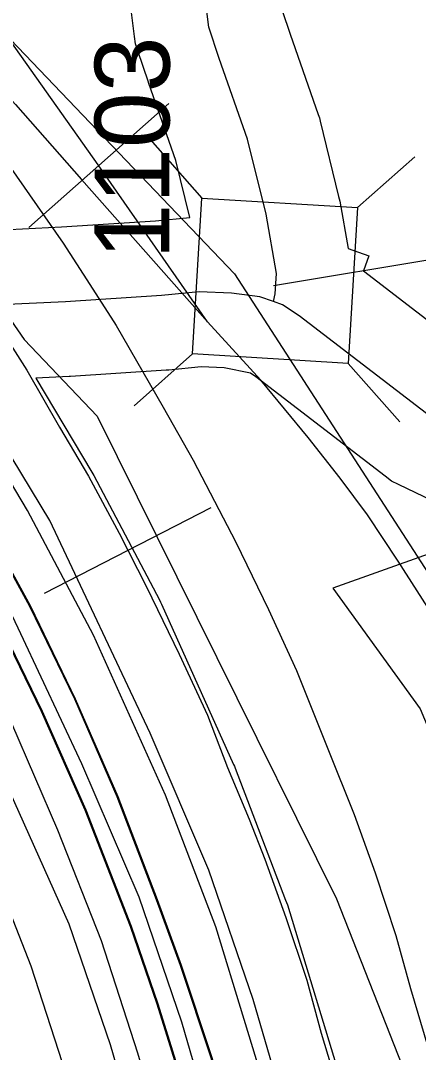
# Model space of a CAD drawing. Extents: x -132.8 to -73.3, y -60 to -26.
# Drawn here: x -123.3422 to -123.1827, y -46.015 to -45.6018 of the extents above; entities that cross this region are included whole.
import ezdxf

# ---------------------------------------------------------------- set-up
doc = ezdxf.new("R2010")
doc.units = 0
for name, color, linetype in [('tdCoDivCarto', 7, 'Continuous'), ('tdCoHydroRiver', 7, 'Continuous'), ('tdCoInt', 7, 'Continuous'), ('tdCoIntCL', 7, 'Continuous'), ('tdCoIntRte', 7, 'Continuous'), ('tdCoPrimary', 7, 'Continuous'), ('tdCoRRCL', 7, 'Continuous'), ('tdCoSecRdNmbr', 7, 'Continuous'), ('tdCoSecRteBand', 7, 'Continuous'), ('tdCoSecRteCL', 7, 'Continuous'), ('tdCoStrucSec', 7, 'Continuous'), ('tdCoStrucSecFHWANum', 7, 'Continuous'), ('tdCoSurfBitum', 7, 'Continuous'), ('tdCoSurfGravel', 7, 'Continuous')]:
    doc.layers.add(name, color=color, linetype=linetype)

msp = doc.modelspace()

# ---------------------------------------------------------------- linework, layer by layer
at = {"layer": 'tdCoDivCarto'}
for p, q in [((-123.33816, -45.83648), (-123.36405, -45.78914)), ((-123.35754, -45.82933), (-123.33362, -45.87841)), ((-123.32016, -45.87348), (-123.33816, -45.83648)), ((-123.30314, -45.91269), (-123.32016, -45.87348)), ((-123.33362, -45.87841), (-123.31611, -45.91786)), ((-123.28736, -45.95387), (-123.30314, -45.91269)), ((-123.31611, -45.91786), (-123.29786, -45.96447)), ((-123.27774, -45.98026), (-123.28736, -45.95387)), ((-123.29786, -45.96447), (-123.28725, -45.99555)), ((-123.26541, -46.01725), (-123.27774, -45.98026)), ((-123.28725, -45.99555), (-123.27542, -46.03328))]:
    msp.add_line(p, q, dxfattribs=at)
for points in [[(-123.68659, -45.35046), (-123.65626, -45.39214), (-123.63078, -45.42835), (-123.578, -45.5011), (-123.49194, -45.6244), (-123.43842, -45.69986), (-123.4113, -45.73883), (-123.38516, -45.78001), (-123.35754, -45.82933), (-123.33362, -45.87841), (-123.31611, -45.91786), (-123.29786, -45.96447), (-123.28725, -45.99555), (-123.27542, -46.03328), (-123.26259, -46.08161), (-123.25544, -46.11416), (-123.24829, -46.15239), (-123.24459, -46.17754), (-123.23152, -46.27051), (-123.22903, -46.28875)], [(-123.68659, -45.35046), (-123.65626, -45.39214), (-123.63078, -45.42835), (-123.578, -45.5011), (-123.49194, -45.6244), (-123.43842, -45.69986), (-123.4113, -45.73883), (-123.38516, -45.78001), (-123.35754, -45.82933), (-123.33362, -45.87841), (-123.31611, -45.91786), (-123.29786, -45.96447), (-123.28725, -45.99555), (-123.27542, -46.03328), (-123.26259, -46.08161), (-123.25544, -46.11416), (-123.24829, -46.15239), (-123.24459, -46.17754), (-123.23152, -46.27051), (-123.22903, -46.28875)], [(-123.68659, -45.35046), (-123.65626, -45.39214), (-123.63078, -45.42835), (-123.578, -45.5011), (-123.49194, -45.6244), (-123.43842, -45.69986), (-123.4113, -45.73883), (-123.38516, -45.78001), (-123.35754, -45.82933), (-123.33362, -45.87841), (-123.31611, -45.91786), (-123.29786, -45.96447), (-123.28725, -45.99555), (-123.27542, -46.03328), (-123.26259, -46.08161), (-123.25544, -46.11416), (-123.24829, -46.15239), (-123.24459, -46.17754), (-123.23152, -46.27051), (-123.22903, -46.28875)], [(-123.21499, -46.28682), (-123.22645, -46.20393), (-123.23187, -46.16694), (-123.2373, -46.13315), (-123.24593, -46.09172), (-123.25752, -46.04363), (-123.26541, -46.01725), (-123.27774, -45.98026), (-123.28736, -45.95387), (-123.30314, -45.91269), (-123.32016, -45.87348), (-123.33816, -45.83648), (-123.36405, -45.78914), (-123.39463, -45.73957), (-123.4299, -45.68803), (-123.47552, -45.62366), (-123.5172, -45.56448), (-123.59438, -45.45794), (-123.61855, -45.42416), (-123.66037, -45.36362)], [(-123.21499, -46.28682), (-123.22645, -46.20393), (-123.23187, -46.16694), (-123.2373, -46.13315), (-123.24593, -46.09172), (-123.25752, -46.04363), (-123.26541, -46.01725), (-123.27774, -45.98026), (-123.28736, -45.95387), (-123.30314, -45.91269), (-123.32016, -45.87348), (-123.33816, -45.83648), (-123.36405, -45.78914), (-123.39463, -45.73957), (-123.4299, -45.68803), (-123.47552, -45.62366), (-123.5172, -45.56448), (-123.59438, -45.45794), (-123.61855, -45.42416), (-123.66037, -45.36362)], [(-123.21499, -46.28682), (-123.22645, -46.20393), (-123.23187, -46.16694), (-123.2373, -46.13315), (-123.24593, -46.09172), (-123.25752, -46.04363), (-123.26541, -46.01725), (-123.27774, -45.98026), (-123.28736, -45.95387), (-123.30314, -45.91269), (-123.32016, -45.87348), (-123.33816, -45.83648), (-123.36405, -45.78914), (-123.39463, -45.73957), (-123.4299, -45.68803), (-123.47552, -45.62366), (-123.5172, -45.56448), (-123.59438, -45.45794), (-123.61855, -45.42416), (-123.66037, -45.36362)]]:
    msp.add_lwpolyline(points, dxfattribs=at)
at = {"layer": 'tdCoHydroRiver'}
msp.add_lwpolyline([(-122.72845, -45.73825), (-122.82597, -45.78451), (-122.87849, -45.80044), (-123.04289, -45.81019), (-123.11745, -45.82394), (-123.12674, -45.81738), (-123.15965, -45.8086), (-123.21702, -45.82913), (-123.18202, -45.87741), (-123.1746, -45.89497), (-123.15487, -45.9239), (-123.1249, -45.98308), (-123.11897, -45.99744), (-123.10673, -46.01197), (-123.07532, -46.07593), (-123.05246, -46.1649), (-123.0467, -46.18556), (-123.0436, -46.18722), (-123.02978, -46.26017), (-123.01499, -46.29686)], dxfattribs=at)
at = {"layer": 'tdCoInt'}
for points in [[(-123.19689, -47.64969), (-123.15587, -47.57914), (-123.13025, -47.51594), (-123.10652, -47.38398), (-123.1111, -47.00162), (-123.11448, -46.89262), (-123.12468, -46.76865), (-123.21401, -46.12989), (-123.22788, -46.06626), (-123.24899, -45.99383), (-123.26669, -45.94208), (-123.2903, -45.88715), (-123.33052, -45.80193), (-123.37601, -45.72709), (-123.50419, -45.54213), (-123.69017, -45.28281)], [(-123.29698, -47.69009), (-123.24768, -47.61769), (-123.20987, -47.55265), (-123.1882, -47.49918), (-123.16657, -47.37891), (-123.17109, -47.00292), (-123.17443, -46.89512), (-123.1843, -46.77553), (-123.27313, -46.14041), (-123.28606, -46.08107), (-123.30621, -46.01194), (-123.32272, -45.96367), (-123.36923, -45.86024), (-123.38334, -45.83056), (-123.42644, -45.75965), (-123.55308, -45.57692), (-123.74046, -45.31564)]]:
    msp.add_lwpolyline(points, dxfattribs=at)
at = {"layer": 'tdCoIntCL'}
msp.add_lwpolyline([(-123.17972, -46.59078), (-123.22232, -46.28778), (-123.22859, -46.24315), (-123.24357, -46.13515), (-123.25697, -46.07366), (-123.2776, -46.00289), (-123.29471, -45.95288), (-123.31767, -45.89945), (-123.3421, -45.84743), (-123.35693, -45.81624), (-123.36969, -45.7954), (-123.40123, -45.74337), (-123.47655, -45.63373), (-123.52863, -45.55953), (-123.52868, -45.55946), (-123.63292, -45.41411), (-123.64916, -45.39147), (-123.68187, -45.34586)], dxfattribs=at)
at = {"layer": 'tdCoIntRte'}
for points in [[(-123.68697, -45.35046), (-123.65664, -45.39214), (-123.63116, -45.42835), (-123.57838, -45.5011), (-123.49232, -45.6244), (-123.4388, -45.69986), (-123.41168, -45.73883), (-123.38554, -45.78001), (-123.35792, -45.82933), (-123.334, -45.87841), (-123.31649, -45.91786), (-123.29824, -45.96447), (-123.28763, -45.99555), (-123.2758, -46.03328), (-123.26297, -46.08161), (-123.25582, -46.11416), (-123.24867, -46.15239), (-123.24497, -46.17754), (-123.2319, -46.27051), (-123.22941, -46.28875), (-123.21858, -46.36792), (-123.21513, -46.39283), (-123.20083, -46.49764)], [(-123.68697, -45.35046), (-123.65664, -45.39214), (-123.63116, -45.42835), (-123.57838, -45.5011), (-123.49232, -45.6244), (-123.4388, -45.69986), (-123.41168, -45.73883), (-123.38554, -45.78001), (-123.35792, -45.82933), (-123.334, -45.87841), (-123.31649, -45.91786), (-123.29824, -45.96447), (-123.28763, -45.99555), (-123.2758, -46.03328), (-123.26297, -46.08161), (-123.25582, -46.11416), (-123.24867, -46.15239), (-123.24497, -46.17754), (-123.2319, -46.27051), (-123.22941, -46.28875), (-123.21858, -46.36792), (-123.21513, -46.39283), (-123.20083, -46.49764)], [(-123.18638, -46.49542), (-123.19699, -46.42144), (-123.21104, -46.31811), (-123.21537, -46.28682), (-123.22683, -46.20393), (-123.23225, -46.16694), (-123.23768, -46.13315), (-123.24631, -46.09172), (-123.2579, -46.04363), (-123.26579, -46.01725), (-123.27812, -45.98026), (-123.28774, -45.95387), (-123.30352, -45.91269), (-123.32054, -45.87348), (-123.33854, -45.83648), (-123.36443, -45.78914), (-123.39501, -45.73957), (-123.43028, -45.68803), (-123.4759, -45.62366), (-123.51757, -45.56448), (-123.59476, -45.45794), (-123.61893, -45.42416), (-123.66075, -45.36362)], [(-123.18638, -46.49542), (-123.19699, -46.42144), (-123.21104, -46.31811), (-123.21537, -46.28682), (-123.22683, -46.20393), (-123.23225, -46.16694), (-123.23768, -46.13315), (-123.24631, -46.09172), (-123.2579, -46.04363), (-123.26579, -46.01725), (-123.27812, -45.98026), (-123.28774, -45.95387), (-123.30352, -45.91269), (-123.32054, -45.87348), (-123.33854, -45.83648), (-123.36443, -45.78914), (-123.39501, -45.73957), (-123.43028, -45.68803), (-123.4759, -45.62366), (-123.51757, -45.56448), (-123.59476, -45.45794), (-123.61893, -45.42416), (-123.66075, -45.36362)]]:
    msp.add_lwpolyline(points, dxfattribs=at)
at = {"layer": 'tdCoPrimary'}
for points in [[(-123.68659, -45.35046), (-123.65626, -45.39214), (-123.63078, -45.42835), (-123.578, -45.5011), (-123.49194, -45.6244), (-123.43842, -45.69986), (-123.4113, -45.73883), (-123.38516, -45.78001), (-123.35754, -45.82933), (-123.33362, -45.87841), (-123.31611, -45.91786), (-123.29786, -45.96447), (-123.28725, -45.99555), (-123.27542, -46.03328), (-123.26259, -46.08161), (-123.25544, -46.11416), (-123.24829, -46.15239), (-123.24459, -46.17754), (-123.23152, -46.27051), (-123.22903, -46.28875)], [(-123.68659, -45.35046), (-123.65626, -45.39214), (-123.63078, -45.42835), (-123.578, -45.5011), (-123.49194, -45.6244), (-123.43842, -45.69986), (-123.4113, -45.73883), (-123.38516, -45.78001), (-123.35754, -45.82933), (-123.33362, -45.87841), (-123.31611, -45.91786), (-123.29786, -45.96447), (-123.28725, -45.99555), (-123.27542, -46.03328), (-123.26259, -46.08161), (-123.25544, -46.11416), (-123.24829, -46.15239), (-123.24459, -46.17754), (-123.23152, -46.27051), (-123.22903, -46.28875)], [(-123.68659, -45.35046), (-123.65626, -45.39214), (-123.63078, -45.42835), (-123.578, -45.5011), (-123.49194, -45.6244), (-123.43842, -45.69986), (-123.4113, -45.73883), (-123.38516, -45.78001), (-123.35754, -45.82933), (-123.33362, -45.87841), (-123.31611, -45.91786), (-123.29786, -45.96447), (-123.28725, -45.99555), (-123.27542, -46.03328), (-123.26259, -46.08161), (-123.25544, -46.11416), (-123.24829, -46.15239), (-123.24459, -46.17754), (-123.23152, -46.27051), (-123.22903, -46.28875), (-123.21821, -46.36792), (-123.21475, -46.39283), (-123.20045, -46.49764)], [(-123.21499, -46.28682), (-123.22645, -46.20393), (-123.23187, -46.16694), (-123.2373, -46.13315), (-123.24593, -46.09172), (-123.25752, -46.04363), (-123.26541, -46.01725), (-123.27774, -45.98026), (-123.28736, -45.95387), (-123.30314, -45.91269), (-123.32016, -45.87348), (-123.33816, -45.83648), (-123.36405, -45.78914), (-123.39463, -45.73957), (-123.4299, -45.68803), (-123.47552, -45.62366), (-123.5172, -45.56448), (-123.59438, -45.45794), (-123.61855, -45.42416), (-123.66037, -45.36362)], [(-123.21499, -46.28682), (-123.22645, -46.20393), (-123.23187, -46.16694), (-123.2373, -46.13315), (-123.24593, -46.09172), (-123.25752, -46.04363), (-123.26541, -46.01725), (-123.27774, -45.98026), (-123.28736, -45.95387), (-123.30314, -45.91269), (-123.32016, -45.87348), (-123.33816, -45.83648), (-123.36405, -45.78914), (-123.39463, -45.73957), (-123.4299, -45.68803), (-123.47552, -45.62366), (-123.5172, -45.56448), (-123.59438, -45.45794), (-123.61855, -45.42416), (-123.66037, -45.36362)], [(-123.186, -46.49542), (-123.19661, -46.42144), (-123.21066, -46.31811), (-123.2127, -46.3034), (-123.21499, -46.28682), (-123.22645, -46.20393), (-123.23187, -46.16694), (-123.2373, -46.13315), (-123.24593, -46.09172), (-123.25752, -46.04363), (-123.26541, -46.01725), (-123.27774, -45.98026), (-123.28736, -45.95387), (-123.30314, -45.91269), (-123.32016, -45.87348), (-123.33816, -45.83648), (-123.36405, -45.78914), (-123.39463, -45.73957), (-123.4299, -45.68803), (-123.47552, -45.62366), (-123.5172, -45.56448), (-123.59438, -45.45794), (-123.61855, -45.42416), (-123.66037, -45.36362)]]:
    msp.add_lwpolyline(points, dxfattribs=at)
at = {"layer": 'tdCoRRCL'}
for p, q in [((-123.28278, -45.63489), (-123.33893, -45.68461)), ((-123.33258, -45.83102), (-123.26583, -45.79683))]:
    msp.add_line(p, q, dxfattribs=at)
for points in [[(-124.56441, -39.58277), (-124.59502, -40.99697), (-124.62126, -41.69986), (-124.64443, -42.5874), (-124.61743, -42.70169), (-124.59894, -42.77948), (-124.57448, -42.87004), (-124.36447, -43.41034), (-124.28789, -43.62059), (-124.20724, -43.85618), (-124.00071, -44.40901), (-123.83109, -44.9246), (-123.75422, -45.12382), (-123.67243, -45.25532), (-123.34073, -45.72941), (-123.31155, -45.76015), (-123.21558, -45.95355), (-123.18597, -46.02848), (-123.11918, -46.43252), (-123.02482, -47.17174), (-122.96612, -47.70495)], [(-123.31114, -45.65953), (-123.45627, -45.45467), (-123.61223, -45.2604)], [(-123.59516, -45.34231), (-123.56501, -45.38032), (-123.5346, -45.41859), (-123.50026, -45.46028), (-123.44574, -45.52371), (-123.39593, -45.57903), (-123.34429, -45.63539), (-123.31777, -45.66533)], [(-123.57309, -45.34093), (-123.54714, -45.37632), (-123.51765, -45.41905), (-123.48815, -45.46178), (-123.45801, -45.50411), (-123.42786, -45.54645), (-123.40584, -45.57686), (-123.38382, -45.60726), (-123.35446, -45.64908), (-123.3251, -45.69089), (-123.31449, -45.7074), (-123.30387, -45.72392), (-123.285, -45.75655), (-123.27307, -45.77779), (-123.2559, -45.81068), (-123.24279, -45.83769), (-123.23152, -45.86206), (-123.21907, -45.89339), (-123.20845, -45.91974), (-123.20006, -45.94307), (-123.19167, -45.96823), (-123.18591, -45.98947), (-123.17883, -46.0128)], [(-123.60889, -45.35881), (-123.58294, -45.3942), (-123.52396, -45.47966), (-123.46367, -45.56433), (-123.41963, -45.62515), (-123.36091, -45.70877), (-123.33967, -45.7418), (-123.32657, -45.76461), (-123.31503, -45.78427), (-123.30271, -45.80707), (-123.2917, -45.82857), (-123.27859, -45.85557), (-123.26732, -45.87995), (-123.2592, -45.90092), (-123.25055, -45.92163), (-123.24425, -45.93762), (-123.23587, -45.96095), (-123.22748, -45.98612), (-123.22171, -46.00735), (-123.21463, -46.03068)], [(-123.56021, -45.37027), (-123.43616, -45.51551), (-123.2564, -45.70322), (-123.09102, -45.9584), (-122.94435, -46.26514), (-122.79504, -46.53094), (-122.75778, -46.61553), (-122.7491, -46.64573), (-122.73718, -46.67287), (-122.72843, -46.82139), (-122.77817, -47.57893), (-122.78529, -47.67024)], [(-122.83836, -46.4665), (-122.87322, -46.40896), (-122.9149, -46.33819), (-122.92211, -46.32639), (-122.94085, -46.29388), (-122.9651, -46.24866), (-122.98634, -46.20777), (-123.01216, -46.15823), (-123.03116, -46.12061), (-123.05921, -46.06621), (-123.07717, -46.03122), (-123.10744, -45.97197), (-123.1292, -45.92951), (-123.14729, -45.89386), (-123.16092, -45.86856), (-123.1756, -45.84208), (-123.19081, -45.81823), (-123.20313, -45.79975), (-123.214, -45.78507), (-123.22685, -45.76868), (-123.24586, -45.74575), (-123.26722, -45.72242), (-123.31114, -45.65953)], [(-122.83836, -46.4665), (-122.87322, -46.40896), (-122.9149, -46.33819), (-122.92211, -46.32639), (-122.94085, -46.29388), (-122.9651, -46.24866), (-122.98634, -46.20777), (-123.01216, -46.15823), (-123.03116, -46.12061), (-123.05921, -46.06621), (-123.07717, -46.03122), (-123.10744, -45.97197), (-123.1292, -45.92951), (-123.14729, -45.89386), (-123.16092, -45.86856), (-123.1756, -45.84208), (-123.19081, -45.81823), (-123.20313, -45.79975), (-123.214, -45.78507), (-123.22685, -45.76868), (-123.24586, -45.74575), (-123.26722, -45.72242), (-123.31777, -45.66533)]]:
    msp.add_lwpolyline(points, dxfattribs=at)
at = {"layer": 'tdCoSecRteBand'}
for points in [[(-123.23858, -46.53338), (-123.25535, -46.41378), (-123.25535, -46.41376), (-123.25535, -46.41375), (-123.27187, -46.29518), (-123.27638, -46.2635), (-123.28906, -46.17437), (-123.29699, -46.1292), (-123.30636, -46.08763), (-123.31376, -46.05848), (-123.32385, -46.02414), (-123.33798, -45.98054), (-123.35496, -45.93749), (-123.37295, -45.896), (-123.39108, -45.85951), (-123.41145, -45.82235), (-123.43991, -45.77509), (-123.46362, -45.73928), (-123.4885, -45.7027), (-123.57287, -45.58389), (-123.64653, -45.48115), (-123.73701, -45.35592)], [(-123.22115, -45.35859), (-123.22918, -45.44018), (-123.23557, -45.53125), (-123.23558, -45.53142), (-123.23559, -45.53159), (-123.23868, -45.56942), (-123.23847, -45.58852), (-123.23733, -45.5977), (-123.23415, -45.60723), (-123.22288, -45.63931), (-123.2224, -45.64067), (-123.22206, -45.64208), (-123.21466, -45.67217), (-123.21442, -45.67313), (-123.21425, -45.6741), (-123.2109, -45.693), (-123.20251, -45.69595), (-123.20464, -45.70202), (-123.16192, -45.73476)], [(-123.45149, -45.57533), (-123.38865, -45.66405), (-123.38838, -45.66443), (-123.38812, -45.66481), (-123.3721, -45.68899), (-123.3709, -45.68839), (-123.36628, -45.68767), (-123.35518, -45.68594), (-123.35359, -45.68569), (-123.35197, -45.68562), (-123.32584, -45.6844), (-123.28814, -45.68198), (-123.27437, -45.68062), (-123.27998, -45.65782), (-123.29084, -45.62688), (-123.29092, -45.62665), (-123.29099, -45.62643), (-123.29519, -45.61385), (-123.29613, -45.61103), (-123.29649, -45.60808), (-123.29822, -45.59427)], [(-123.16034, -45.80206), (-123.19068, -45.78752), (-123.19348, -45.78617), (-123.19595, -45.78428), (-123.24794, -45.74444), (-123.25008, -45.74301), (-123.26058, -45.74081), (-123.26976, -45.74046), (-123.28278, -45.74174), (-123.28329, -45.74179), (-123.2838, -45.74182), (-123.32227, -45.74429), (-123.32253, -45.74431), (-123.32278, -45.74432), (-123.33616, -45.74494), (-123.31364, -45.78265), (-123.31325, -45.78331), (-123.31288, -45.78399), (-123.2865, -45.8338), (-123.28605, -45.83466), (-123.28565, -45.83553), (-123.2568, -45.89965), (-123.25645, -45.90043), (-123.25614, -45.90123), (-123.23592, -45.954), (-123.23555, -45.95497), (-123.23524, -45.95597), (-123.21256, -46.0302)]]:
    msp.add_lwpolyline(points, dxfattribs=at)
at = {"layer": 'tdCoSecRteCL'}
for points in [[(-123.24076, -45.71431), (-123.24009, -45.71114), (-123.2396, -45.70301), (-123.24379, -45.67933), (-123.25119, -45.64925), (-123.26253, -45.61694), (-123.26673, -45.60436), (-123.26845, -45.59055), (-123.2687, -45.56836), (-123.26549, -45.52915), (-123.25908, -45.43766), (-123.25094, -45.35504), (-123.2428, -45.29685), (-123.23713, -45.24654), (-123.23491, -45.21842), (-123.23393, -45.17946), (-123.23121, -45.13877), (-123.21018, -45.08941)], [(-123.20887, -46.52922), (-123.22564, -46.40961), (-123.24216, -46.29099), (-123.24667, -46.25927), (-123.25942, -46.16966), (-123.26756, -46.1233), (-123.27718, -46.08064), (-123.28482, -46.05055), (-123.29518, -46.01529), (-123.30973, -45.97041), (-123.32724, -45.92602), (-123.34574, -45.88335), (-123.36448, -45.84562), (-123.38544, -45.8074), (-123.41454, -45.75906), (-123.43871, -45.72257), (-123.46386, -45.68557), (-123.54845, -45.56646), (-123.62218, -45.46363), (-123.71269, -45.33835)], [(-123.24076, -45.71431), (-123.24626, -45.71238), (-123.2576, -45.7109), (-123.27067, -45.7104), (-123.28571, -45.71188), (-123.32419, -45.71435), (-123.35057, -45.71558), (-123.36167, -45.71731), (-123.36907, -45.72101), (-123.37597, -45.72446), (-123.3819, -45.72851)], [(-122.80582, -45.91805), (-122.82629, -45.91607), (-122.84971, -45.9146), (-122.87832, -45.91533), (-122.91556, -45.91805), (-122.93159, -45.91879), (-122.94416, -45.91829), (-122.95748, -45.91583), (-122.97696, -45.90621), (-123.03146, -45.86429), (-123.08448, -45.82014), (-123.10766, -45.79795), (-123.11827, -45.78981), (-123.12912, -45.78315), (-123.14737, -45.77502), (-123.1777, -45.76047), (-123.23047, -45.72002), (-123.23713, -45.71558), (-123.24076, -45.71431)], [(-123.05973, -47.28302), (-123.05999, -47.28088), (-123.07701, -47.15387), (-123.09452, -47.02663), (-123.11301, -46.89814), (-123.12731, -46.79383), (-123.14433, -46.67028), (-123.16209, -46.5413), (-123.17959, -46.41726), (-123.19636, -46.29519), (-123.20163, -46.25826), (-123.21585, -46.15857), (-123.23089, -46.0767), (-123.24125, -46.03897), (-123.26393, -45.96474), (-123.28416, -45.91196), (-123.31301, -45.84785), (-123.3394, -45.79803), (-123.37195, -45.74353), (-123.3819, -45.72851)]]:
    msp.add_lwpolyline(points, dxfattribs=at)
at = {"layer": 'tdCoStrucSec'}
for points in [[(-123.29023, -45.64941), (-123.26949, -45.67283), (-123.20704, -45.67661)], [(-123.18413, -45.65632), (-123.20704, -45.67661), (-123.21083, -45.73906)], [(-123.29669, -45.75601), (-123.27327, -45.73527), (-123.26949, -45.67283)], [(-123.19009, -45.76247), (-123.21083, -45.73906), (-123.27327, -45.73527)]]:
    msp.add_lwpolyline(points, dxfattribs=at)
at = {"layer": 'tdCoStrucSecFHWANum'}
msp.add_line((-123.14601, -45.69217), (-123.24084, -45.70798), dxfattribs=at)
at = {"layer": 'tdCoSurfBitum'}
msp.add_lwpolyline([(-123.1777, -45.76047), (-123.23047, -45.72002), (-123.23713, -45.71558), (-123.24076, -45.71431), (-123.24626, -45.71238), (-123.2576, -45.7109), (-123.27067, -45.7104), (-123.28571, -45.71188), (-123.32419, -45.71435), (-123.35057, -45.71558), (-123.36167, -45.71731), (-123.36907, -45.72101), (-123.37597, -45.72446), (-123.3819, -45.72851)], dxfattribs=at)
at = {"layer": 'tdCoSurfGravel'}
for points in [[(-123.24667, -46.25927), (-123.25942, -46.16966), (-123.26756, -46.1233), (-123.27718, -46.08064), (-123.28482, -46.05055), (-123.29518, -46.01529), (-123.30973, -45.97041), (-123.32724, -45.92602), (-123.34574, -45.88335), (-123.36448, -45.84562), (-123.38544, -45.8074), (-123.41454, -45.75906), (-123.43871, -45.72257), (-123.46386, -45.68557), (-123.54845, -45.56646), (-123.62218, -45.46363), (-123.71269, -45.33835), (-123.74157, -45.29741)], [(-123.24076, -45.71431), (-123.24009, -45.71114), (-123.2396, -45.70301), (-123.24379, -45.67933), (-123.25119, -45.64925), (-123.26253, -45.61694), (-123.26673, -45.60436), (-123.26845, -45.59055), (-123.2687, -45.56836), (-123.26549, -45.52915), (-123.25908, -45.43766), (-123.25094, -45.35504), (-123.2428, -45.29685)], [(-123.20163, -46.25826), (-123.21585, -46.15857), (-123.23089, -46.0767), (-123.24125, -46.03897), (-123.26393, -45.96474), (-123.28416, -45.91196), (-123.31301, -45.84785), (-123.3394, -45.79803), (-123.37195, -45.74353), (-123.3819, -45.72851), (-123.41313, -45.68139), (-123.47602, -45.59261), (-123.50142, -45.55636), (-123.58773, -45.43429), (-123.67256, -45.31542)]]:
    msp.add_lwpolyline(points, dxfattribs=at)

# ---------------------------------------------------------------- texts
at = {"layer": 'tdCoSecRdNmbr'}
msp.add_text('1103', height=0.03, rotation=89.9077, dxfattribs=at).set_placement((-123.28261, -45.69741))

doc.saveas('drawing.dxf')
